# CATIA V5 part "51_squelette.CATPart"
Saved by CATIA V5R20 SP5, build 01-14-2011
Part number: 51_squelette
Publications: "hauteur", "diametre", "Point.1", "Plan.1", "Plan.2", "Plan yz"
Bounding box of the stored display mesh (mm): x 0 to 0, y 140.362 to 140.362, z -95 to -95
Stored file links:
  C:\Documents and Settings\anizard\Bureau\13\51_squelette.CATPart
  C:\Documents and Settings\anizard\Bureau\13\anizard.CATProduct
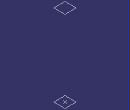
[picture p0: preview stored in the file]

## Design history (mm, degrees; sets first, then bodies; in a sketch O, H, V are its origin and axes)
Parameters
  hauteur = 190 mm
  diametre = 156 mm
Set1
  Point1: linked copy from another document
  Line1: linked copy from another document
Body1 (main body)
  Point2: type OnCurve, Support Line1, RefPoint Point1, Length 95 {= hauteur /2}
  Plane1: type Normal, Curve Line1, RefPoint Point2
  Plane2: type Offset, RefPlane Plane1, Offset 190 {= hauteur}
